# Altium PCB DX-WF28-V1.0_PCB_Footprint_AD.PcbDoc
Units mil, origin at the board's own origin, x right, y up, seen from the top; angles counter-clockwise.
Board outline 1181.1 x 1574.8 mil, 2 copper layers (Top, Bottom), stack 12.7 mil thick; 1 components, 0 nets, 23 pads, 0 vias.
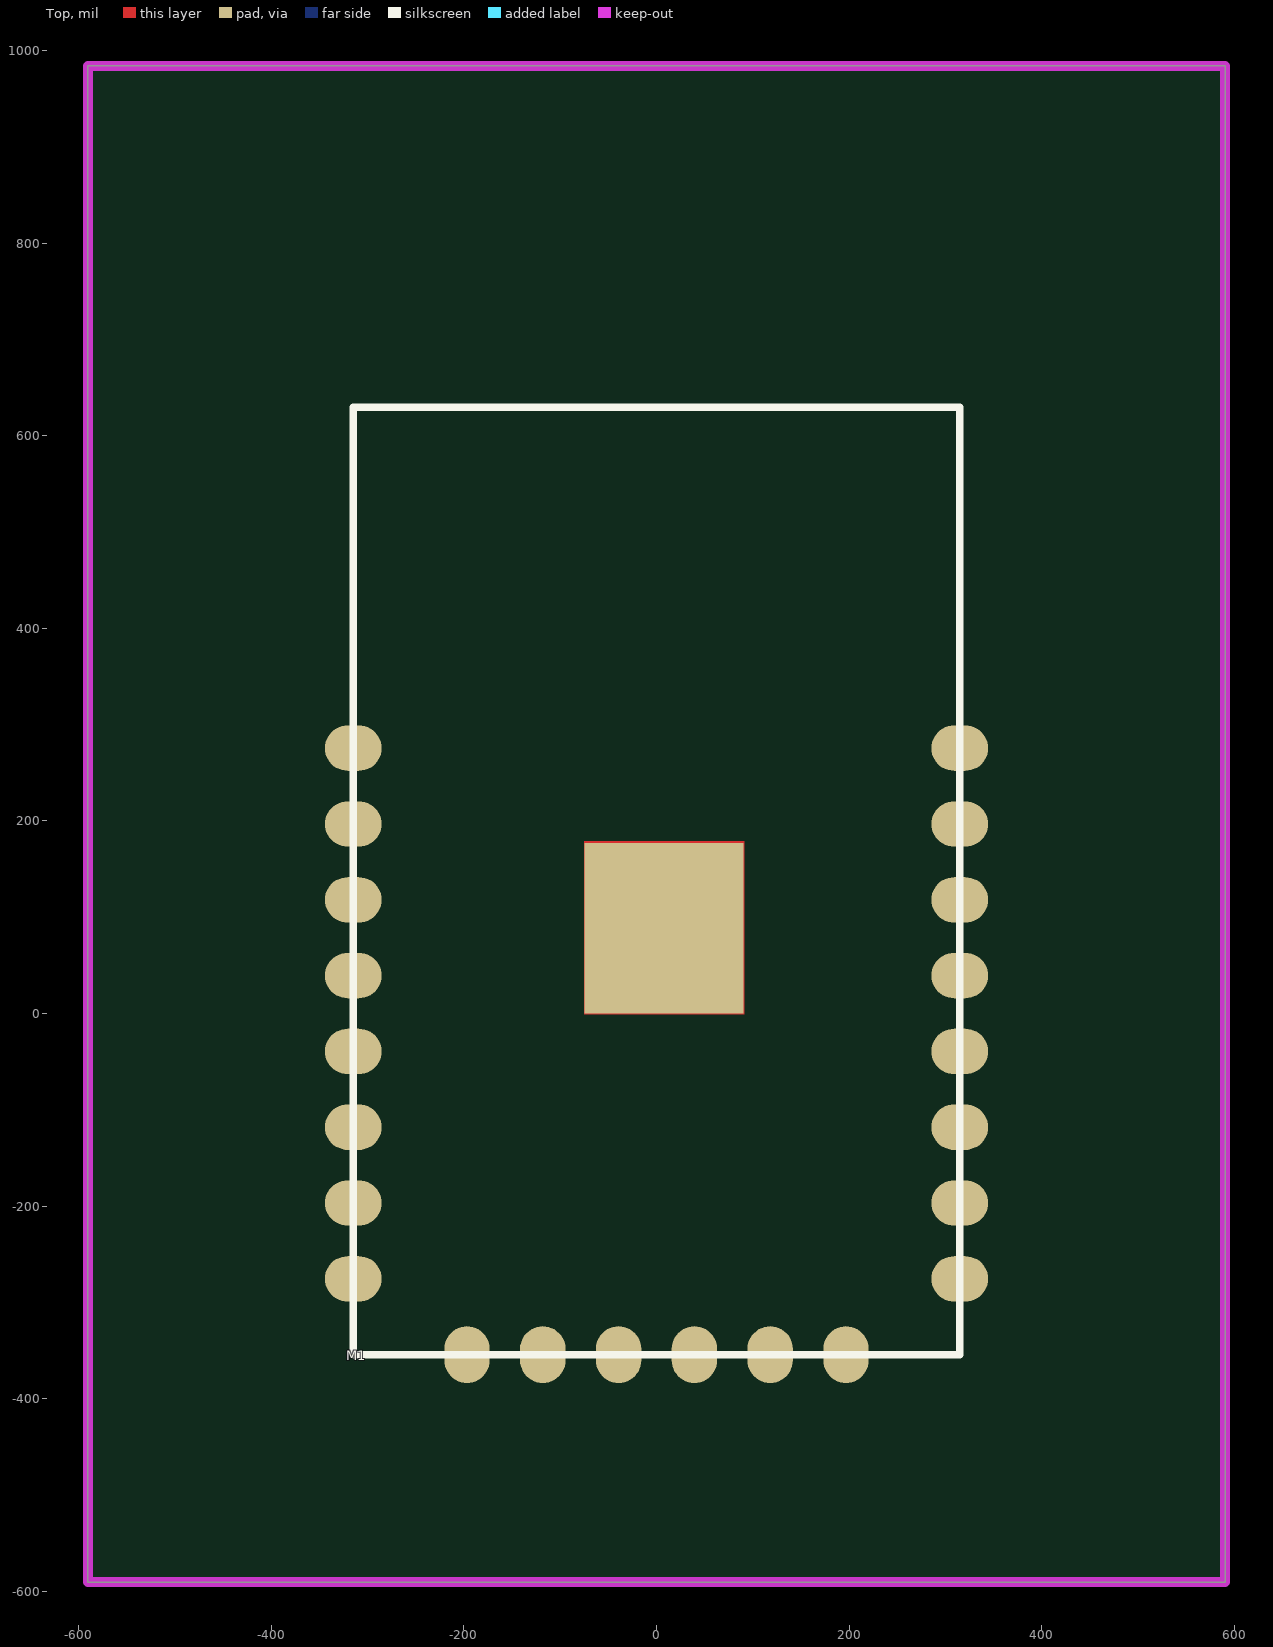
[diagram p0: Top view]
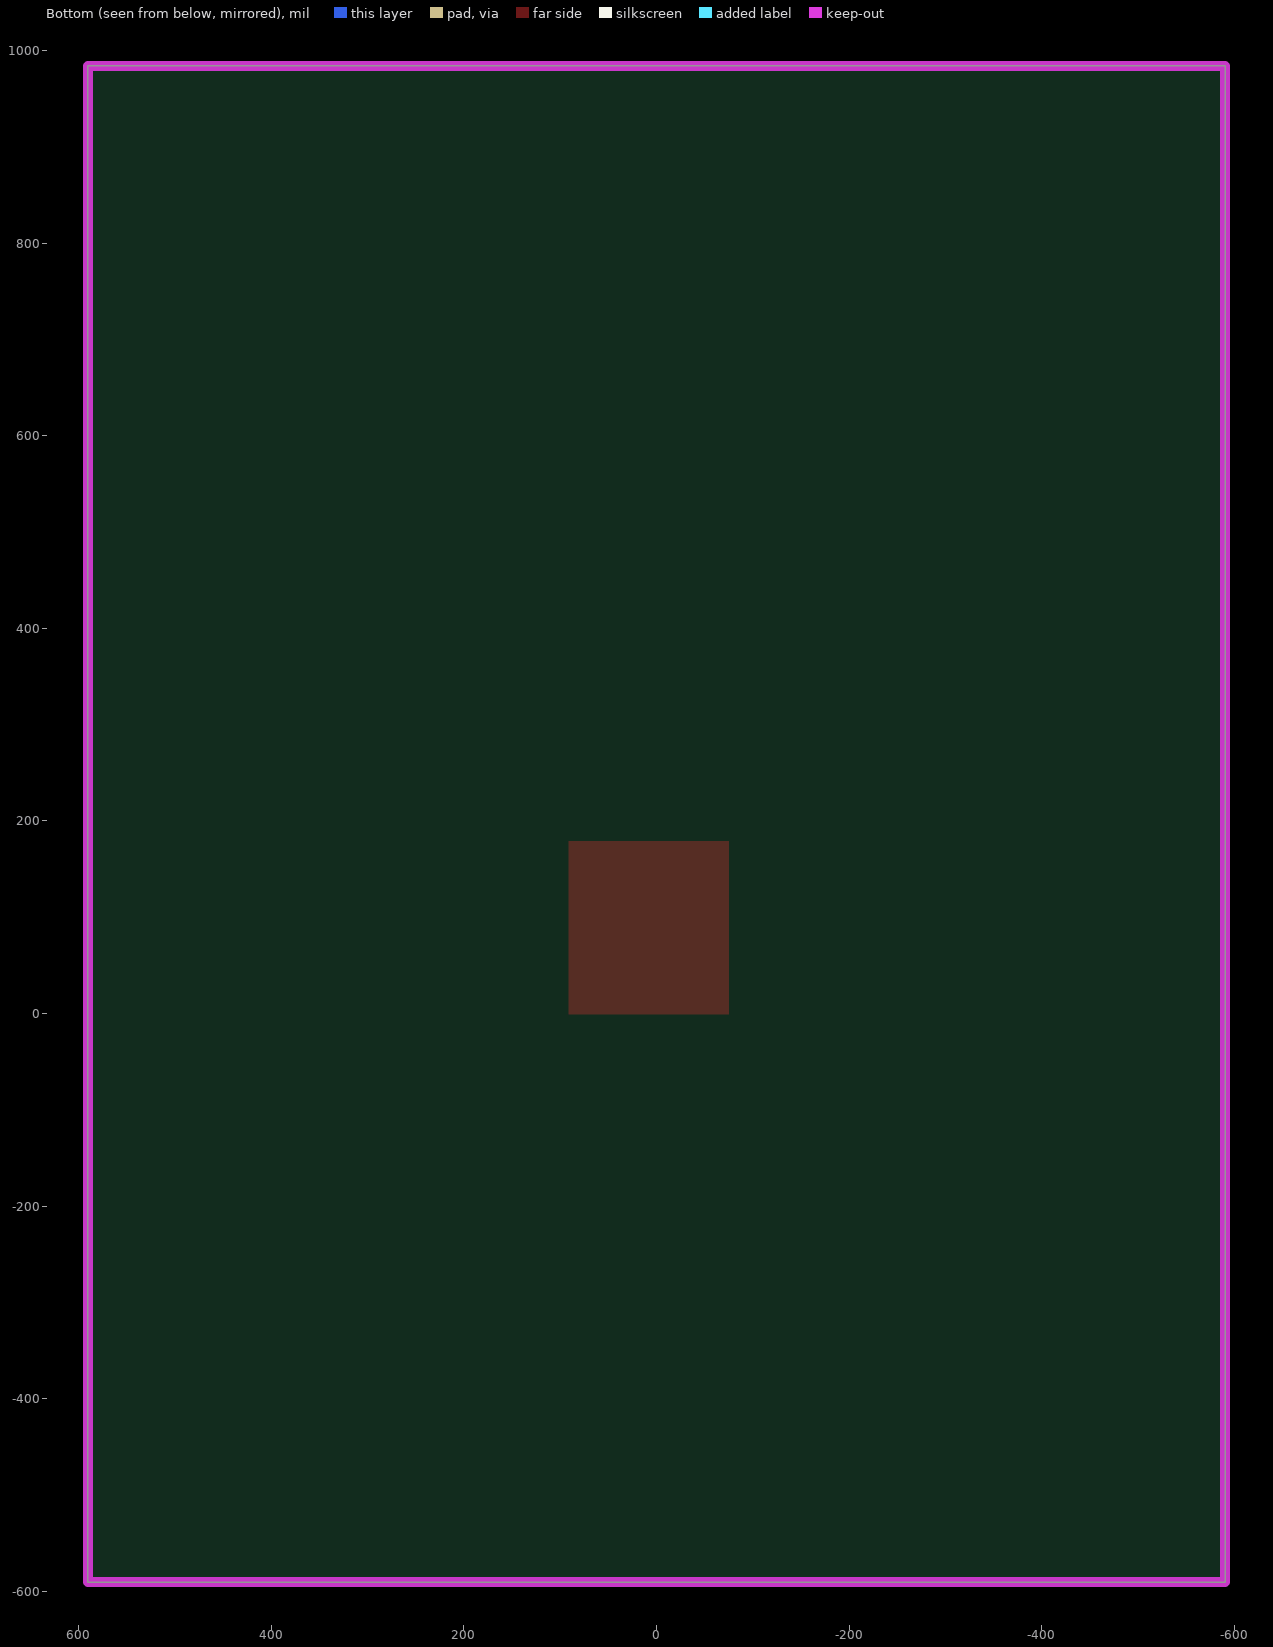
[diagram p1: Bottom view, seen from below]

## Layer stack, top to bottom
Solder Mask Top: solder mask 0.4, Solder Resist, Dk 3.5
Top: signal copper 1.35
Dielectric 1: dielectric 10, FR-4, Dk 4.3
Bottom: signal copper 1.35
Solder Mask Bottom: solder mask 0.4, Solder Resist, Dk 3.5

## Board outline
-590.55,984.25 590.55,984.25 590.55,-590.55 -590.55,-590.55

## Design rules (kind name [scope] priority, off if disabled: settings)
Clearance "Clearance - Default - DEFAULT - Via" [IsVia vs IsVia] p1: gap=6 ignorepadtopadclearanceinfootprint=FALSE
Clearance "Clearance - Default - DEFAULT- SMD" [IsVia vs IsSMTPin] p2: gap=6 ignorepadtopadclearanceinfootprint=FALSE
Clearance "Clearance - Default - DEFAULT - Net" [All] p3: gap=6 ignorepadtopadclearanceinfootprint=FALSE except(10: Arc-Hole Track-Hole SMDPad-Hole THPad-Hole Via-Hole Fill-Hole Poly-Hole Region-Hole Text-Text Text-Hole)
ComponentClearance "ComponentClearance - Default - DEFAULT" [All] p1: gap=6 collisioncheckmode=3 verticalgap=10 showdistances=FALSE
FanoutControl Fanout_SOIC [IsSOIC] p1: bgadir=Out bgaviamode=Centered fanoutstyle=Auto fanoutdirection=Alternating viagrid=1 // Fanout_SOIC (Default Rule)
FanoutControl Fanout_Small [(CompPinCount < 5)] p2: bgadir=Out bgaviamode=Centered fanoutstyle=Auto fanoutdirection=OutThenIn viagrid=1 // Fanout_Small (Default Rule)
FanoutControl Fanout_LCC [IsLCC] p3: bgadir=Out bgaviamode=Centered fanoutstyle=Auto fanoutdirection=Alternating viagrid=1 // Fanout_LCC (Default Rule)
FanoutControl Fanout_BGA [IsBGA] p4: bgadir=Out bgaviamode=Centered fanoutstyle=Auto fanoutdirection=Alternating viagrid=1 // Fanout_BGA (Default Rule)
HoleToHoleClearance "HoleToHoleClearance - Default - DEFAULT" [All] p1: gap=6 allowstackedmicrovias=TRUE
Length "Default Length" [All] p1: maxlimit=50000 minlimit=0
MaxMinImpedance "Default Impedance" [All] p1: minimum=50.00 maximum=150.0
ParallelSegment "Default Parallel Segment Same Layer" [All] p1: limit=1000 gap=200
ParallelSegment "Default Parallel Segment Adjasent" [All] p2: limit=1000 gap=200
RoutingLayers "RoutingLayers - Default - DEFAULT" [All] p1: top layer_v5=TRUE bottom layer_v5=TRUE
RoutingPriority "RoutingPriority - Default - DEFAULT" [All] p1: routingpriority=3
RoutingTopology "Default Routing Topology" [All] p1: topology=Shortest
RoutingVias "RoutingVias - Default - DEFAULT" [All] p1: holewidth=37 width=55 viastyle="Through Hole" minholewidth=37 minwidth=55 maxholewidth=37 maxwidth=55
SMDToCorner "SMDToCorner - Default - DEFAULT" [All] p1: distance=60000
SolderMaskExpansion [All] p1: expansion=4 istentingtop=FALSE
Width "Default Width" [All] p1: maxlimit=6 minlimit=6 preferedwidth=6
18 further rules are at their usual default settings.

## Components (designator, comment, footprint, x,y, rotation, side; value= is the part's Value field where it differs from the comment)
M1 "DX-WF28" DX-WF28 0,0 r0 top

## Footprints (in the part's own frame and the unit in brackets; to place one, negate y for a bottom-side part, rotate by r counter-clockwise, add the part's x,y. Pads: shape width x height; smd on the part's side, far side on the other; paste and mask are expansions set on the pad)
DX-WF28 [mm]
  oval 1.5x1.2 smd: 1(-8,7) 2(-8,5) 3(-8,3) 4(-8,1) 5(-8,-1) 6(-8,-3) 7(-8,-5) 8(-8,-7) 15(8,-7) 16(8,-5) 17(8,-3) 18(8,-1) 19(8,1) 20(8,3) 21(8,5) 22(8,7)
  oval 1.2x1.5 smd: 9(-5,-9) 10(-3,-9) 11(-1,-9) 12(1,-9) 13(3,-9) 14(5,-9)
  rect 4.2x4.5 smd: 23(0.2,2.25)
  Top region: -1.904,4.551 -1.904,-0.021 2.312,-0.021 2.312,4.551 -1.904,4.551
  silkscreen extent -8,-9 8,16

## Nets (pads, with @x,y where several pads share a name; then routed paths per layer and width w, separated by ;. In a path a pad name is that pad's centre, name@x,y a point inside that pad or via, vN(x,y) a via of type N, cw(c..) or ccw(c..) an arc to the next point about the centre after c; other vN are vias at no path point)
pads on no net: M1.1 M1.2 M1.3 M1.4 M1.5 M1.6 M1.7 M1.8 M1.9 M1.10 M1.11 M1.12 M1.13 M1.14 M1.15 M1.16 M1.17 M1.18 M1.19 M1.20 M1.21 M1.22 M1.23

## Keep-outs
Keep-Out Layer:
  the board outline again, w10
